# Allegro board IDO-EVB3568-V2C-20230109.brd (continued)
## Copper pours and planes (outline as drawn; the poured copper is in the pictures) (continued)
GND on BOTTOM (solid shape): 56.16,23.3 56.26,23.24 56.23,23.13 52.83,19.73 52.83,18.8 52.35,18.8 51.9,18.35 51.79,18.33 51.73,18.42 51.73,19.27 55.76,23.3
GND on BOTTOM (solid shape): 82.34,74.36 82.37,74.27 82.32,74.2 82.23,74.12 82.15,74.01 79.57,74.01 79.33,74.25 79.3,74.37 79.4,74.43 82.27,74.43
GND on BOTTOM (solid shape): 19.41,51.13 19.53,51.15 19.59,51.06 19.59,49.47 20.12,49.47 20.54,49.05 20.54,48.94 20.57,48.91 20.58,48.85 20.53,48.82 18.69,48.82 18.53,48.67 18.06,48.67 18.06,49.78
GND on BOTTOM (solid shape): 21.93,26.31 22,26.4 22.11,26.38 22.75,25.73 23.95,25.73 24.32,25.37 24.32,24.7 23.3,23.68 23.3,22.92 23.22,22.84 23.11,22.82 23.05,22.91 23.05,24.98 21.93,26.09
GND on BOTTOM (solid shape): 53.79,24.83 53.84,24.8 53.83,24.74 52.16,23.08 51.96,23.08 51.9,23.15 51.83,23.21 51.78,23.29 51.83,23.38 51.9,23.44 51.96,23.51 52.33,23.51 53.65,24.83
GND on BOTTOM (solid shape): 89.09,23.79 90.33,23.79 90.43,23.73 90.41,23.62 90.23,23.44 85.97,23.44 85.88,23.51 85.9,23.62 86.43,24.14 88.73,24.14
GND on BOTTOM (solid shape): 111.15,68.77 111.23,68.73 111.25,68.64 111.24,68.43 111.33,68.24 108.96,65.87 108.03,65.87 107.93,65.94 107.95,66.05 110.68,68.77
GND on BOTTOM (solid shape): 19.91,37.83 19.95,37.68 20.03,37.56 20.06,37.49 20.04,37.42 19.96,37.31 19.92,37.18 19.92,37.14 19.73,37.14 19.61,37.26 19.53,37.26 19.53,37.36 17.9,37.36 17.9,37.65 19.53,37.65 19.53,37.84 19.56,37.87 19.91,37.87
GND on BOTTOM (solid shape): 27.81,66.62 27.83,66.51 27.74,66.45 27.66,66.45 27.05,67.06 23.46,67.06 23.36,67.11 23.38,67.22 23.44,67.34 23.47,67.47 23.48,67.51 26.92,67.51
GND on BOTTOM (solid shape): 19.89,39.33 19.95,39.19 20.05,39.07 20.09,39 20.06,38.92 19.97,38.81 19.92,38.68 19.91,38.64 19.53,38.64 19.53,38.64 19.53,38.86 17.9,38.86 17.9,39.15 19.53,39.15 19.53,39.37 19.54,39.37 19.89,39.37
GND on BOTTOM (solid shape): 23.96,14.55 24,14.6 24.05,14.59 25.11,13.53 27.89,13.53 28.16,13.26 28.16,12.82 28.65,12.33 28.65,11.49 29.27,10.87 29.27,10.74 29.21,10.65 29.1,10.67 26.48,13.3 25.18,13.3 23.96,14.51
GND on BOTTOM (solid shape): 28.51,16.61 28.57,16.71 28.68,16.68 29.02,16.35 29.02,15.21 30.16,14.06 30.16,12.79 30.59,12.36 30.59,11.62 30.53,11.53 30.42,11.55 29.94,12.03 29.94,12.86 29.45,13.35 29.45,13.8 28.51,14.74
GND on BOTTOM (solid shape): 55.55,13.28 55.87,13.28 57.14,13.28 57.31,13.28 58.37,13.28 58.47,13.18 58.47,12.91 58.34,12.78 56.44,12.78 56.14,13.08 55.47,13.08 55.16,12.78 55.12,12.78 54.82,13.08 54.65,13.08 54.55,13.14 54.58,13.25 54.84,13.52 54.84,13.73 55.1,13.73
GND on BOTTOM (solid shape): 19.93,36.33 19.97,36.22 20.04,36.12 20.07,36.05 20.04,35.98 19.94,35.85 19.9,35.71 19.89,35.66 19.59,35.66 19.53,35.72 19.53,35.86 17.9,35.86 17.9,36.07 18.04,36.07 18.12,36.15 19.53,36.15 19.53,36.25 19.61,36.25 19.73,36.37 19.92,36.37
GND on BOTTOM (solid shape): 19.94,40.85 19.97,40.73 20.03,40.62 20.05,40.55 20.02,40.49 19.93,40.35 19.88,40.18 19.88,40.14 19.56,40.14 19.53,40.16 19.53,40.36 18.02,40.36 17.99,40.39 17.95,40.39 17.95,40.6 18,40.65 19.53,40.65 19.53,40.89 19.93,40.89
GND on BOTTOM (solid shape): 46.87,61.28 46.96,61.22 46.94,61.11 46.31,60.48 46.31,59.97 46.27,59.96 46.14,59.92 46.03,59.85 46,59.84 45.96,59.85 45.85,59.92 45.72,59.96 45.68,59.97 45.68,60.14 46.82,61.28
GND on BOTTOM (solid shape): 79.59,47.44 79.64,47.53 79.75,47.52 79.86,47.47 79.99,47.45 80.02,47.44 80.04,47.4 80.04,46.92 83.34,43.61 83.35,43.55 83.31,43.52 83.24,43.52 79.59,47.18
GND on BOTTOM (solid shape): 61.8,37.78 61.89,37.72 61.87,37.61 61.18,36.92 57.21,36.92 56.96,37.17 56.93,37.27 57,37.34 57.22,37.49 57.32,37.74 57.33,37.78
GND on BOTTOM (solid shape): 87.06,28.97 87.12,28.98 87.15,28.94 87.15,28.9 85.75,27.51 85.75,26.62 76.48,17.35 76.48,13.16 70.05,6.73 38.74,6.73 35.92,9.55 35.92,9.58 35.95,9.63 36,9.62 37.59,8.03 38.05,8.03 39.19,6.88 70.05,6.88 76.07,12.9 76.07,17.09 85.62,26.65 85.62,27.53
GND on BOTTOM (solid shape): 123.24,63.69 123.3,63.78 123.41,63.76 123.64,63.53 123.65,63.53 123.65,60.94 125.17,59.41 125.2,59.34 125.16,59.26 125.06,59.13 125,58.97 125,58.93 124.79,58.93 123.24,60.48
GND on BOTTOM (solid shape): 100.27,18.89 100.27,13.28 100.2,13.19 100.09,13.21 99.78,13.52 99.78,17.71 97.96,19.54 97.96,19.57 97.94,19.78 97.84,19.96 97.82,20.07 97.91,20.13 99.03,20.13
GND on BOTTOM (solid shape): 55.16,54.92 55.22,54.83 55.22,54.49 53.92,53.19 53.85,53.19 53.75,53.25 53.77,53.36 53.87,53.46 53.87,53.71 53.91,53.75 54.31,53.75 54.74,54.17 54.74,54.76 54.78,54.77 54.92,54.81 55.04,54.9
GND on BOTTOM (solid shape): 48.65,27.08 48.71,27.17 48.82,27.15 49.72,26.25 49.72,25.04 49.68,24.96 49.59,24.94 49.2,24.89 48.98,24.56 48.98,24.52 48.65,24.52
GND on BOTTOM (solid shape): 119.21,66.56 119.28,66.66 119.39,66.63 119.47,66.55 120.66,66.55 120.73,66.62 120.78,66.63 120.82,66.58 120.82,64.13 121.09,63.85 121.09,59.89 121.03,59.8 120.92,59.82 120.91,59.83 119.52,59.83 119.21,60.13 119.21,60.65 120.92,60.65 120.92,62.89 119.21,62.89
GND on BOTTOM (solid shape): 82.24,71.71 85.17,71.71 86.09,70.8 86.09,69.97 86.9,69.16 87.18,69.16 87.2,69.1 87.2,69.04 86.3,69.04 84.54,70.81 82.49,70.81 82.4,70.85 82.39,70.94 82.34,71.26 82.09,71.46 82.05,71.47 82.05,71.63 81.35,72.34 81.32,72.45 81.42,72.51 81.44,72.51
GND on BOTTOM (solid shape): 42.32,22.76 42.41,22.79 42.48,22.73 42.66,22.51 42.92,22.43 43.01,22.37 42.99,22.26 42.9,22.16 41.38,22.16 41.11,22.43 40.46,22.43 40.38,22.47 40.37,22.56 40.38,22.65 42.2,22.65 42.2,22.75 42.31,22.75
GND on BOTTOM (solid shape): 99.69,43.81 99.69,43.3 100.45,42.54 102.84,42.54 102.9,42.49 102.9,42.35 102.48,41.94 100.58,41.94 100.2,41.56 100.2,41.29 100.14,41.19 100.03,41.22 100.01,41.24 97.98,41.24 97.77,41.45 97.74,41.55 97.82,41.62 98.09,41.78 98.2,42.08 98.2,42.1 98.72,42.61 98.72,44.68 98.77,44.73
GND on BOTTOM (solid shape): 57.23,21.77 57.33,21.71 57.3,21.59 55.65,19.94 55.65,18.92 55.42,18.69 55.42,17.87 55.35,17.79 55.35,17.13 55.42,17.05 55.42,16.67 55.38,16.67 55.24,16.62 55.13,16.54 55.09,16.52 55.06,16.54 54.9,16.64 54.71,16.68 54.68,16.69 54.66,16.73 54.66,16.83 54.81,16.99 54.81,17.45 54.66,17.6 54.66,18.74 54.49,18.92 54.49,19.2 57.05,21.77
GND on BOTTOM (solid shape): 67.71,46.25 67.82,46.27 67.88,46.18 67.88,45.75 66.36,44.23 66.36,43.01 65.01,41.66 65.01,41.08 64.86,40.93 64,40.93 63.92,40.98 63.91,41.08 63.94,41.16 63.95,41.26 63.95,41.28 64.08,41.41 64.39,41.41 64.39,41.5 64.49,41.5 64.49,42.2 64.68,42.4 64.68,43.45 64.43,43.7 64.41,43.81 64.5,43.87 65.31,43.87 65.34,43.88
GND on BOTTOM (solid shape): 76.15,50.75 76.18,50.73 76.39,50.58 76.64,50.56 76.64,50.56 77.99,50.56 78.2,50.35 78.23,50.26 78.17,50.18 78,50.07 77.89,49.91 77.87,49.87 75.26,49.87 75.17,49.94 75.19,50.05 75.82,50.68 75.84,50.68 75.98,50.69 76.11,50.74
GND on BOTTOM (solid shape): 77.25,75.25 77.28,75.14 77.18,75.08 74.11,75.08 73.77,74.73 73.65,74.73 73.57,74.78 73.56,74.88 73.59,75.22 73.38,75.49 72.95,75.92 70.21,75.92 69.65,75.36 69.13,75.36 69.04,75.45 68.92,75.51 68.86,75.58 68.89,75.67 69.32,76.1 76.4,76.1
GND on BOTTOM (solid shape): 21.96,14.16 22.03,14.06 22.03,13.55 22.5,13.09 22.52,12.98 22.43,12.92 20.13,12.92 19.82,13.23 19.8,13.35 19.92,13.39 21,13.43 21.85,14.11
GND on BOTTOM (solid shape): 10.41,62.63 10.41,62.15 10.92,61.64 10.94,61.53 10.85,61.47 10.79,61.47 10.24,60.92 10.24,60.34 10.49,60.09 10.49,58.52 10.21,58.52 10.21,59.01 8.82,60.4 7.81,60.4 7.72,60.45 7.73,60.56 7.84,60.83 7.85,61.12 7.91,61.23 8.03,61.21 8.33,60.91 9.25,60.91 9.65,61.31 9.65,62.71 9.86,62.92 10.13,62.92
GND on BOTTOM (solid shape): 22.52,24.76 22.52,22.92 21.53,21.93 21.53,18.75 21.46,18.65 21.35,18.67 21.01,19.01 19.87,19.01 18.76,20.13 18.76,21.3 19.52,22.06 19.52,24.73 20.03,25.24 20.12,25.27 20.2,25.2 20.76,24.88 21.12,25.42 21.12,25.44 21.48,25.8
GND on BOTTOM (solid shape): 62.32,35.19 62.38,35.28 62.49,35.26 62.53,35.22 62.59,35.19 63.36,34.42 66.86,34.42 66.87,34.41 67,34.4 67.12,34.41 67.21,34.39 67.25,34.31 67.25,33.59 67.15,33.49 62.83,33.49 62.45,33.11 59.36,33.11 59.27,33.16 59.28,33.27 59.34,33.42 59.35,33.6 59.35,33.62 59.57,33.85 61.02,33.85 62.32,35.14
GND on BOTTOM (solid shape): 92.24,17.91 93.11,17.91 93.42,17.6 93.44,17.49 93.35,17.42 91.48,17.42 91.14,17.57 90.79,17.42 89.68,17.42 89.03,16.77 89.03,15.41 88.91,15.23 88.88,15.02 88.88,14.99 88.83,14.94 88.77,15 88.77,18.02 88.1,18.69 83.7,18.69 83.57,18.83 83.55,18.94 83.65,19 91.15,19
GND on BOTTOM (solid shape): 62.88,64.1 62.99,64.13 63.06,64.03 63.06,62.75 62.87,62.56 62.87,62.55 62.76,62.44 62.75,62.44 62.63,62.32 62.32,62.32 62.24,62.23 62.13,62.21 62.06,62.31 62.06,62.36 62.1,62.37 62.4,62.77 62.18,63.22 62.13,63.3 62.16,63.38
GND on BOTTOM (solid shape): 52.37,17.19 52.46,17.22 52.53,17.17 52.58,17.11 52.64,17.05 52.67,16.98 52.64,16.9 52.39,16.65 52.39,14.39 51.93,13.93 51.17,13.93 51.08,13.99 51.1,14.1 51.23,14.42 51.11,14.74 51.1,14.85 51.19,14.91 51.5,14.91 52.13,15.54 52.13,16.96
GND on BOTTOM (solid shape): 51.27,22.26 51.31,22.34 51.4,22.36 51.47,22.34 51.55,22.33 51.64,22.27 51.61,22.16 49.7,20.24 49.7,19.71 48.65,19.71 48.65,19.79 48.67,19.83 48.7,19.84 49.06,20.02 49.16,20.41 49.18,20.5 49.26,20.54 49.62,20.54 51.27,22.19
GND on BOTTOM (solid shape): 94.73,22.15 94.73,20.99 94.67,20.9 94.56,20.92 94.5,20.98 92.36,20.98 91.98,21.36 91.98,21.39 92,21.43 92.03,21.44 92.5,21.99 91.89,22.38 91.88,22.38 86.63,22.38 86.56,22.44 86.55,22.5 86.6,22.53 90.61,22.53 91.15,23.06 93.82,23.06
GND on BOTTOM (solid shape): 101.61,69.31 101.63,69.26 101.58,69.23 101.48,69.23 100.42,70.29 97.15,70.29 95.93,69.08 95.18,69.08 95.1,69.11 95.08,69.2 94.7,69.79 94.14,69.37 94.13,69.33 93.84,69.33 92.8,68.29 92.7,68.29 92.61,68.35 92.63,68.46 94.57,70.4 100.53,70.4
GND on BOTTOM (solid shape): 69.29,60.28 69.28,60.25 69.41,59.81 69.84,59.68 69.93,59.66 69.96,59.58 69.96,59.47 68.59,58.09 68.48,58.07 68.41,58.17 68.41,59.02 68.54,59.15 68.54,59.7 68.57,59.71 68.83,59.99 68.8,60.37 68.8,60.47 68.89,60.52 69.05,60.52
GND on BOTTOM (solid shape): 18.76,18.36 18.82,18.46 18.93,18.44 19.4,17.97 20.54,17.97 22.03,16.48 22.03,16.05 21.96,15.95 21.85,15.99 20.39,16.78 18.95,15.99 18.83,15.94 18.76,16.04
GND on BOTTOM (solid shape): 32.59,27.62 32.68,27.56 32.66,27.45 32.58,27.37 31.94,27.37 31.18,26.6 31.18,24.67 31.01,24.5 30.43,24.5 30.43,23.74 30.37,23.64 30.26,23.66 29.18,24.74 27,24.74 26.59,25.15 26.59,26.52 26.48,26.63 26.46,26.74 26.56,26.8 26.99,27.01 27.03,27.48 27.04,27.58 27.12,27.62
GND on BOTTOM (solid shape): 87.9,28.28 88.02,28.3 88.06,28.18 87.96,26.67 88.7,25.36 88.73,25.25 88.63,25.18 86,25.18 84.89,24.07 84.87,24.07 83.77,22.98 83.77,22.96 81.6,20.79 81.6,20.51 81.12,20.03 80.74,20.03 77.91,17.2 77.91,15.55 77.64,15.28 77.53,15.26 77.47,15.35 77.47,16.97 86.69,26.19 86.69,27.08
GND on BOTTOM (solid shape): 85.05,75.2 85.17,75.08 85.2,75 85.15,74.93 85.05,74.3 85.69,74.27 85.76,74.3 85.84,74.27 85.95,74.19 86.07,74.15 86.09,74.14 86.14,74.1 86.03,73.98 84.65,73.98 84.41,74.23 84.41,74.97 84.37,75.01 84.42,75.06 84.44,75.06 84.72,75.12 84.96,75.28 84.97,75.3 85.05,75.3
GND on BOTTOM (solid shape): 11.17,40.19 11.2,40.17 11.23,40.11 11.27,40.06 11.28,40.03 11.27,40 11.43,39.25 12.1,39.6 12.11,39.64 12.4,39.64 12.4,39.21 12.8,38.81 14.03,38.81 14.43,39.21 14.43,39.56 14.47,39.6 16.04,39.6 16.04,39.31 17.86,39.31 17.86,39.16 16.04,39.16 16.04,38.61 11.69,38.61 10.87,39.42 10.87,40.05 10.9,40.12 10.97,40.15 11.05,40.16 11.14,40.19
GND on BOTTOM (solid shape): 88.99,69.22 89.01,69.11 88.92,69.04 88.13,69.04 88.05,69.08 88.03,69.16 88.01,69.37 87.9,69.55 87.84,70.16 87.23,70.07 87.16,70.03 87.08,70.06 86.85,70.29 86.85,71.11 85.59,72.37 85.58,72.43 85.62,72.46 85.74,72.46
GND on BOTTOM (solid shape): 61.93,54.22 61.99,54.2 62.18,54.1 62.4,54.09 62.48,54.07 62.52,53.99 62.52,49.23 61.84,48.55 61.39,48.55 61.3,48.6 61.3,48.7 61.36,48.95 61.29,49.2 61.29,49.3 61.38,49.35 61.52,49.35 62.1,49.93 62.1,53.19 61.38,53.91 61.36,54.03 61.47,54.09 61.68,54.1 61.86,54.2
GND on BOTTOM (solid shape): 39.69,12.11 39.73,12.09 40.05,11.95 40.37,12.07 40.45,12.09 40.52,12.06 40.63,11.97 40.78,11.92 40.82,11.91 40.82,11.07 41.42,10.46 43.77,10.46 44.68,11.38 45.15,11.38 45.24,11.32 45.22,11.21 43.53,9.51 40.78,9.51 40.58,9.71 40.58,10.4 40.14,10.83 39.07,10.83 38.85,11.06 38.85,11.98 38.91,12.07 39.01,12.06 39.34,11.95 39.65,12.09
GND on BOTTOM (solid shape): 88.42,10.39 88.51,10.32 88.48,10.21 88.35,9.61 88.91,9.37 88.91,9.37 92.41,9.37 92.5,9.31 92.48,9.2 92.24,8.97 91.25,8.97 90.42,8.14 90.42,6.6 90.57,6.45 90.31,6.18 87.61,6.18 87.52,6.26 87.55,6.37 87.75,6.78 87.51,7.17 87.51,9.99 87.91,10.39
GND on BOTTOM (solid shape): 52.91,41.28 53.02,41.31 53.09,41.21 53.09,38.37 54.97,36.48 54.98,36.43 54.99,36.38 54.99,36.33 54.57,35.91 54.46,35.89 54.39,35.98 54.39,36.43 54.14,36.69 54.14,36.71 53.53,37.24 53.32,36.46 53.33,36.42 53.31,36.39 53.17,36.01 53.36,35.66 53.38,35.64 53.38,35.57 52.97,35.16 52.86,35.14 52.79,35.23 52.79,41.16
GND on BOTTOM (solid shape): 108.92,28.45 109.02,28.43 109.23,28.21 109.79,28.21 109.88,28.15 109.86,28.04 106.29,24.47 106.29,17.76 101.35,12.83 101.24,12.81 101.18,12.9 101.18,19.11 99.57,20.72 99.57,23.13 99.61,23.2 99.69,23.23 99.98,23.27 100.19,23.47 100.19,23.47 100.36,23.64 100.36,24.04 100.4,24.13 100.49,24.14 100.99,24.24 101.12,24.72 101.12,24.73 101.12,25.57 103.54,27.99 105.76,27.99 105.77,27.99 105.9,27.97 106.04,27.99 106.04,27.99 108.52,27.99 108.61,28.08 108.61,28.08 108.76,28.21 108.85,28.38
GND on BOTTOM (solid shape): 53.64,19.46 53.69,19.47 53.73,19.42 53.73,18.6 53.9,18.43 53.9,16.71 53.88,16.67 53.85,16.66 53.4,16.25 53.71,15.73 53.74,15.72 53.74,15.63 53.74,15.63 53.74,13.73 53.82,13.66 53.8,13.55 53.66,13.41 52.41,13.41 52.32,13.47 52.34,13.58 52.92,14.16 52.92,16.42 53.3,16.81 53.3,17.09 53.28,17.75 52.62,17.77 52.57,17.76 52.54,17.8 52.54,17.91 52.66,18.03 53.19,18.03 53.59,18.43 53.59,19.41
GND on BOTTOM (solid shape): 125.75,51.86 125.86,51.88 125.92,51.79 125.92,51.36 125.88,51.35 125.5,50.68 126.26,50.53 126.37,50.54 126.43,50.45 126.43,49.59 126.31,49.47 125.8,49.47 125.71,49.52 125.71,49.62 125.69,50.13 125.23,50.33 125.21,50.33 124.93,50.61 124.93,51.13 124.97,51.21 125.06,51.23 125.51,51.33 125.67,51.76 125.67,51.78
GND on BOTTOM (solid shape): 77.14,72.14 77.17,72.06 77.12,71.98 76.97,71.36 77.61,71.29 78.27,71.39 78.02,72.01 77.99,72.02 77.99,72.11 78.05,72.21 78.16,72.18 78.61,71.74 80.87,71.74 81.1,71.5 81.13,71.43 81.1,71.36 80.98,71.16 80.97,70.94 80.96,70.85 80.88,70.81 77.03,70.81 76.5,71.34 76.5,71.63 75.83,72.3 75.81,72.41 75.9,72.47 76.82,72.47
GND on BOTTOM (solid shape): 90.79,16.76 91.14,16.62 91.48,16.76 93.46,16.76 93.78,16.45 93.78,12.71 92.12,11.05 87.97,11.05 87.92,11.08 87.93,11.14 87.97,11.18 89.95,11.18 90.73,11.95 90.73,14.92 90.73,14.93 90.74,15.17 90.62,15.39 90.6,15.5 90.7,15.56 92.15,15.56 92.22,15.53 92.25,15.45 93.09,15.14 92.66,15.92 92.64,15.92 92.46,16.09 90.66,16.09 90.59,16.16 90.59,16.19 90.57,16.41 90.46,16.59 90.44,16.7 90.53,16.76
GND on BOTTOM (solid shape): 33.89,21.9 34.29,21.5 34.29,19.16 34.01,18.58 34.56,18.25 34.65,18.23 34.68,18.15 34.68,17.55 34.62,17.45 34.51,17.48 33.8,17.45 33.9,16.75 33.9,16.32 33.59,16.01 33.59,14.66 32.91,13.98 32.91,12.94 32.84,12.85 32.73,12.87 32.17,13.43 32.17,13.46 32.02,13.88 31.58,13.99 31.5,14.01 31.46,14.09 31.46,14.66 30.56,15.57 30.56,18.21 30.65,18.21 30.65,19.59 30.68,19.62 32.67,19.62 33.48,20.43 33.51,20.43 33.51,22.39 33.47,22.39 33.47,22.56 33.56,22.64 33.89,22.64
GND on BOTTOM (solid shape): 60.76,34.58 60.85,34.52 60.83,34.41 60.8,34.38 59.35,34.38 58.97,34 58.94,34 58.42,33.66 58.69,33.09 58.74,33.02 58.72,32.92 58.52,32.73 58.49,32.73 58.18,32.67 57.98,32.42 57.9,32.35 57.81,32.38 57.11,33.08 57.11,33.21 57.17,33.96 56.43,33.83 56.34,33.78 56.25,33.83 56.11,33.99 55.91,34.08 55.83,34.14 55.86,34.25 56.19,34.58
GND on BOTTOM (solid shape): 73.26,63.63 73.29,63.54 73.23,63.47 73.05,62.79 73.74,62.66 73.77,62.67 73.81,62.65 73.87,62.6 73.93,62.56 73.99,62.49 73.96,62.4 72.17,60.61 72.16,60.61 72.07,60.57 71.98,60.52 71.88,60.5 71.82,60.6 71.82,61.15 72.22,61.56 72.22,62.49 72.25,62.56 72.32,62.59 72.62,63.43 71.84,63 71.84,62.98 71.8,62.94 71.75,62.92 71.72,62.97 71.72,63.72 71.94,63.94 72.94,63.94
GND on BOTTOM (solid shape): 42.05,14.47 42.96,14.47 43.35,14.2 43.77,14.4 43.85,14.45 43.93,14.42 44.13,14.21 44.52,14.21 44.56,14.16 44.6,14.11 44.63,14 44.53,13.93 41.86,13.93 41.78,13.97 41.76,14.06 41.06,14.59 41.17,13.71 41.18,13.71 41.3,13.6 41.32,13.49 41.22,13.42 40.79,13.42 40.39,13.82 39.8,13.82 39.36,13.38 39.36,12.96 39.34,12.92 39.31,12.91 39.15,12.88 39.01,12.8 38.91,12.79 38.85,12.88 38.85,13.94 39.12,14.21 40.29,14.21 40.85,14.77 41.75,14.77
GND on BOTTOM (solid shape): 51.33,45.72 51.44,45.74 51.5,45.65 51.5,45.46 48.07,42.03 48.07,37.05 48.22,36.9 48.24,36.79 48.15,36.73 46.68,36.73 46.59,36.78 46.59,36.88 45.84,38.01 45.35,36.75 44.83,36.23 44.83,28.33 44.77,28.24 44.66,28.26 44.49,28.43 44.49,33.77 43.65,34.6 43.65,35.95 43.69,36.03 43.78,36.05 44.18,36.08 44.41,36.4 44.41,36.41 44.97,36.97 44.97,37.94 45.55,38.52 45.55,40.17 45.94,40.55 45.94,44.56 45.78,44.72 45.76,44.83 45.85,44.89 50.5,44.89
GND on BOTTOM (solid shape): 9.8,29.19 9.87,29.28 9.98,29.26 11.93,27.3 14.34,27.3 14.6,27.04 14.6,24.5 15.49,23.61 15.49,19.42 16.84,18.08 16.84,18.01 16.81,17.97 16.75,17.98 14.63,20.1 14.63,22.64 12.86,24.41 11.8,24.41 11.6,24.21 11.55,24.16 11.43,24.04 11.43,23.97 11.43,23.96 11.41,23.83 11.43,23.69 11.43,23.68 11.43,23.08 11.43,23.07 11.41,22.94 11.43,22.8 11.43,22.8 11.43,22.19 11.43,22.18 11.41,22.05 11.43,21.91 11.43,21.91 11.43,21.3 11.43,21.29 11.41,21.16 11.43,21.02 11.43,21.02 11.43,20.41 11.43,20.4 11.41,20.27 11.43,20.14 11.43,20.13 11.43,19.68 12.06,19.05 12.95,19.05 14.16,17.84 14.19,17.76 14.16,17.69 14.03,17.5 14,17.27 14.01,17.24 13.91,17.14 13.91,14.73 13.85,14.63 13.74,14.65 13.58,14.75 13.4,14.78 13.33,14.81 13.3,14.88 13.3,15.4 10.95,17.75 10.95,23.66 10.45,24.16 9.58,24.16 9.48,24.22 9.5,24.33 9.8,24.63
GND on BOTTOM (solid shape): 13.11,42.67 13.2,42.62 13.2,42.51 13.12,42.17 13.29,41.87 13.32,41.79 13.29,41.71 13.29,40.97 14.02,41.13 14.09,41.19 14.18,41.16 14.68,40.66 16.04,40.66 16.04,40.41 14.2,40.41 13.67,39.87 13.67,39.57 13.16,39.57 13.16,39.97 12.73,40.4 12.11,40.4 12.11,40.44 11.86,40.8 11.44,40.81 11.4,40.81 11.37,40.84 10.99,41.1 10.57,40.93 10.49,40.89 10.41,40.93 10.19,41.08 9.93,41.09 9.84,41.11 9.8,41.19 9.8,42.41 10.07,42.67
GND on BOTTOM (solid shape): 35.11,16.39 35.22,16.41 35.28,16.32 35.28,14.05 34.98,13.74 34.98,9.09 38.24,5.82 38.26,5.71 38.17,5.65 37.8,5.65 35.37,8.09 31.33,8.09 31.25,8.17 31.22,8.28 31.32,8.35 31.56,8.4 31.74,8.56 31.84,8.56 32.88,9.59 32.88,10.18 32.92,10.26 33.01,10.28 33.49,10.44 33.56,10.94 33.56,11.02 33.62,11.08 33.65,11.08 33.68,11.08 33.71,11.06 34.33,10.83 34.59,11.44 34.58,11.47 34.82,11.71 34.82,15.22 34.85,15.23 35.15,15.62 34.95,16.06 34.9,16.14 34.93,16.22
GND on BOTTOM (solid shape): 106.82,48.53 106.85,48.42 106.75,48.36 106.55,48.33 106.38,48.22 106.31,48.18 106.24,48.22 105.56,48.23 105.55,47.55 105.57,47.44 105.48,47.38 100.6,47.38 99.36,46.13 98.23,46.13 98.14,46.18 98.14,46.28 98.19,46.53 98.11,46.77 98.11,46.82 98.15,46.85 98.21,46.85 98.94,47.59 102.37,47.59 103.15,48.36 103.25,48.39 103.32,48.31 103.65,47.93 104.14,48.05 104.21,48.08 104.28,48.05 104.87,47.97 105.09,48.52 105.1,48.61 105.18,48.65 106.71,48.65
GND on BOTTOM (solid shape): 39.33,19.4 39.43,19.43 39.5,19.36 39.83,19.04 40.28,19.15 42.05,19.15 42.05,18.56 42.41,18.2 42.41,18.2 42.74,17.87 44.94,17.87 45.03,17.82 45.03,17.72 44.92,17.26 45.03,16.8 45.03,16.71 44.97,16.66 44.67,16.29 44.82,15.85 44.85,15.73 44.75,15.67 44.47,15.67 43.82,16.32 40.02,16.32 40.01,16.36 39.39,16.61 39.27,15.95 39.35,15.28 39.98,15.52 39.99,15.56 40.13,15.56 40.23,15.49 40.2,15.38 39.82,15 38.65,15 38.41,14.76 38.3,14.74 38.24,14.83 38.24,18.3
GND on BOTTOM (solid shape): 75.07,62.37 75.16,62.4 75.23,62.34 75.31,62.22 75.41,62.13 75.41,61.66 73.34,59.6 73.34,55.12 73.3,55.04 73.22,55.02 72.66,54.75 72.83,54.16 72.83,53.65 70.87,51.69 70.76,51.67 70.7,51.77 70.7,52.92 71.87,54.09 71.87,54.16 71.68,55.03 71.22,54.27 71.25,54.23 70.37,53.34 70.26,53.32 70.19,53.42 70.19,53.56 70.7,54.07 70.7,57.5 71.82,58.61 71.82,59.7 71.88,59.79 71.98,59.78 72.29,59.67 72.63,59.8 72.66,59.78 73.32,59.82 73.32,60.48 73.29,60.55 73.32,60.62
GND on BOTTOM (solid shape): 13.09,61.61 14.94,61.61 14.94,61.01 15.01,60.93 14.96,60.88 14.94,60.88 14.77,60.85 14.62,60.76 14.3,60.88 13.98,60.76 13.34,60.76 13.28,60.12 13.34,59.49 13.98,59.48 14.3,59.36 14.62,59.48 15.26,59.49 15.32,60.12 15.4,60.31 15.4,60.52 15.4,60.58 15.53,60.58 15.53,60.08 17.39,60.08 17.39,60.63 18.16,60.63 18.29,60.5 18.29,60.31 18.25,60.3 17.96,60.06 17.94,59.67 17.92,59.58 17.84,59.54 17.7,59.54 17.56,59.4 17.45,59.38 17.39,59.47 17.39,59.61 15.53,59.61 15.53,59.13 15.24,59.13 15.14,59.04 13.19,59.04 13.19,58.99 13.12,58.99 12.99,58.87 12.84,58.87 12.74,58.93 12.76,59.04 13.06,59.33 13.06,60.03 12.66,60.43 12.19,60.43 12.19,60.86 11.78,61.27 11.76,61.38 11.86,61.44 12.68,61.44 13.01,61.77 13.09,61.77
GND on BOTTOM (solid shape): outline of 191 points within 72.36,6.18 89.81,19.76
GND on BOTTOM (solid shape): 124.92,34.33 124.92,29.74 125.01,29.64 124.95,29.58 124.92,29.59 121.15,27.8 123.87,24.63 123.95,24.6 123.98,24.53 123.98,23.97 124.03,23.92 124.04,23.86 123.99,23.83 123.12,23.83 119.08,27.87 119.08,29.01 119.1,29.05 119.13,29.06 119.56,29.73 118.77,29.87 118.7,29.84 118.63,29.87 118.48,29.98 118.3,30.02 118.21,30.08 118.24,30.19 120.43,32.38 121.19,32.38 122.06,33.26 122.17,33.28 122.24,33.19 122.24,32.1 123.3,31.03 123.3,31 124.11,30.6 123.71,31.41 123.68,31.41 122.77,32.32 122.77,35.76 123.49,35.76
GND on BOTTOM (solid shape): 98.77,27.16 98.77,21.68 98.31,21.22 97.88,21.22 97.46,21.43 97.07,21.18 97.06,21.18 97.02,21.14 96.96,21.19 96.97,21.22 96.16,21.62 96.56,20.81 96.59,20.82 97.22,20.18 97.25,20.1 97.21,20.02 97.04,19.46 97.55,19.16 97.58,19.16 99.25,17.49 99.25,13.3 99.76,12.79 99.76,9.74 100.34,9.16 100.34,7.83 100.32,7.8 100.21,7.78 100.14,7.86 100.05,8.09 99.85,8.24 99.83,8.26 99.82,8.3 99.34,8.91 98.92,8.25 98.91,8.16 98.83,8.12 98.48,8.12 98.19,7.83 98.08,7.81 98.02,7.9 98.02,18.05 95.64,20.42 95.64,22.53 94.19,23.98 93.98,23.98 93.98,24.45 95.64,26.1 96.41,26.1 96.42,26.1 97.03,26.56 96.42,27.02 96.41,27.02 95.87,27.02 95.77,27.08 95.8,27.19 96.2,27.6 98.33,27.6
GND on BOTTOM (solid shape): 61.82,19.99 61.92,19.93 61.9,19.82 61.04,18.96 60.95,18.93 60.87,18.99 60.18,19.23 60.06,18.51 60.07,18.48 60.06,18.45 60.01,17.9 60.5,17.66 60.6,17.63 60.61,17.53 60.82,16.94 61.43,17.05 61.51,17.09 61.58,17.05 62.33,17.05 62.17,17.78 62.12,17.85 62.14,17.94 62.26,18.06 62.37,18.08 62.43,17.98 62.43,17.93 62.71,17.65 63.17,17.65 63.45,17.93 63.45,18.24 63.77,18.24 63.86,18.17 63.84,18.06 62.27,16.5 62.25,16.5 61.75,16.24 61.84,15.69 61.86,15.58 61.77,15.52 60.59,15.52 59.97,16.14 59.97,17.54 59.3,18.21 59.3,18.21 58.92,18.46 58.5,18.28 58.39,18.24 58.32,18.34 58.32,19.25 59.06,19.99
GND on BOTTOM (solid shape): 28.83,23.13 28.83,22.31 28.83,22.31 29.04,21.76 29.63,21.84 29.69,21.87 29.76,21.85 30.37,21.88 30.45,22.49 30.45,22.59 30.54,22.64 30.94,22.64 30.94,22.39 30.9,22.39 30.9,20.92 29.3,20.92 28.69,20.31 28.66,20.29 28.62,20.31 27.96,20.31 27.93,19.64 27.93,18.92 27.87,18.82 27.76,18.84 27.34,19.27 24.7,19.27 24.57,19.39 24.55,19.5 24.64,19.56 25,19.76 25.07,20.17 25.07,20.18 25.07,20.87 25.69,21.49 25.77,21.52 25.84,21.47 26.15,21.27 26.51,21.35 27.18,21.4 27.14,22.07 27.12,22.11 27.14,22.15 26.88,22.92 26.31,22.35 26.29,22.26 26.21,22.22 26.13,22.21 26.05,22.18 25.95,22.19 25.91,22.28 25.91,22.47 26.81,23.37 28.59,23.37
GND on BOTTOM (solid shape): 78.06,49.34 78.15,49.29 78.25,49.26 78.3,49.25 78.3,47.19 78.23,47.1 78.12,47.12 76.74,48.5 76.74,48.52 76.22,48.86 75.8,48.41 75.78,48.37 75.75,48.36 75.3,47.96 75.6,47.43 75.66,47.35 75.62,47.25 75.56,46.52 76.29,46.6 76.75,46.6 78.91,44.43 78.94,44.32 78.84,44.26 75.36,44.26 75.35,44.3 74.67,44.68 74.54,43.91 74.55,43.88 74.54,43.84 74.66,43.08 75.35,43.43 75.36,43.47 79.11,43.47 81.43,41.16 81.45,41.05 81.36,40.98 77.18,40.98 75.89,39.69 75.78,39.67 75.72,39.76 75.72,41.69 75.36,42.05 75.36,42.07 74.54,42.4 74.87,41.58 74.89,41.58 75.06,41.42 75.06,39.71 74.89,39.54 74.87,39.54 74.69,39.5 74.53,39.4 74.31,39.4 74.21,39.46 74.24,39.57 74.26,39.59 74.26,48.71 74.89,49.34
GND on BOTTOM (solid shape): outline of 84 points within 52.9,10.64 70.3,21.03
GND on BOTTOM (solid shape): outline of 99 points within 78.82,44.28 94.4,60.92
GND on BOTTOM (solid shape): outline of 489 points within 37.65,8.18 83.53,26.49
GND on BOTTOM (solid shape): outline of 862 points within 100.8,7.04 128.3,29.25
GND on BOTTOM (solid shape): outline of 874 points within 32.49,22.81 45.15,45.51
GND on BOTTOM (solid shape): outline of 3634 points within 3.39,14.31 34.48,70.07
GND on BOTTOM (solid shape): outline of 6369 points within 0.25,0.25 134.82,89.76
GND on TOP: 104.7,9.09 105.46,9.09 105.82,8.74 109.8,8.74 110.06,8.99 112.55,8.99 112.73,8.81 112.73,8.05 112.32,7.65 111.25,7.65 111.02,7.87 104.7,7.87 104.57,8 104.57,8.97
GND on TOP: 86.18,24.08 88.47,24.08 88.72,23.83 88.72,23.44 88.6,23.32 85.67,23.32 85.55,23.44 85.55,23.65 84.91,24.28 84.91,25.6 85.09,25.78 87.4,25.78 87.5,25.68 87.5,25.27 87.38,25.15 86.13,25.15 86,25.02 86,24.26
GND on TOP: 27.25,13.54 28.02,13.54 28.14,13.41 29.41,13.41 30.43,12.4 30.43,11.89 30.3,11.76 29.16,11.76 28.91,12.01 27.76,12.01 27.25,11.51 26.37,11.51 26.24,11.63 26.24,13.16 26.37,13.28 27,13.28
GND on TOP: 41.99,29.79 46.05,29.79 46.18,29.67 46.18,28.78 46.05,28.65 41.99,28.65 41.86,28.78 41.86,29.67
GND on BOTTOM: 121.36,56.85 122.25,56.85 122.5,56.59 122.5,54.43 122.38,54.31 121.49,54.31 121.36,54.18 121.36,53.04 121.23,52.91 120.73,52.91 120.6,53.04 120.6,56.08
GND on L2-GND: 0.38,89 0.57,89.45 1.02,89.64 134.06,89.64 134.51,89.45 134.7,89 134.7,1.02 134.51,0.57 134.06,0.38 1.02,0.38 0.57,0.57 0.38,1.02 ; 2 cut-outs
GND on L3-POW: 134.06,89.64 134.51,89.45 134.7,89 134.7,1.02 134.51,0.57 134.06,0.38 1.02,0.38 0.57,0.57 0.38,1.02 0.38,89 0.57,89.45 1.02,89.64 ; 5 cut-outs
GND_EARTH on BOTTOM (solid shape): 17.27,78.74 17.27,77.65 16.1,76.48 16.1,72.29 15.49,71.68 12.37,71.68 11.76,72.29 11.76,74.12 11.38,74.5 9.73,74.5 6.76,71.53 3.51,71.53 1.83,73.2 1.83,75.77 3.81,77.75 12.01,77.75 13.72,79.45 16.56,79.45
GND_EARTH on BOTTOM: 0.25,71.55 0.25,89 0.48,89.54 1.02,89.76 51.33,89.76 51.71,89.38 51.71,77.77 50.98,77.04 49.61,77.04 49.2,77.44 35.79,77.44 35.26,76.91 30.96,76.91 30.48,77.39 16.94,77.39 14.35,74.8 9.55,74.8 6.3,71.55
GND_EARTH on L3-POW: 15.51,76.86 14.43,77.94 14.43,89.41 14.66,89.64 51.41,89.64 51.54,89.64 51.77,89.41 51.77,77.65 50.98,76.86
GND_IN on TOP: 18.08,10.26 18.39,10.26 18.59,10.06 18.59,8.43 18.21,8.05 12.8,8.05 12.8,9.83 13.03,10.06 17.88,10.06
GND_IN on TOP: 11.89,13.54 12.14,13.28 12.14,12.32 10.54,10.72 9.35,10.72 8.99,11.07 8.99,13.34 9.19,13.54
GND_IN on TOP: 10.62,63.32 8.79,63.32 8.56,63.55 8.56,67.34 8.66,67.44 9.94,67.44 9.94,67.42 10.08,67.28 10.08,66.17 10.72,65.53 10.72,63.42
GND_IN on TOP: 14.4,73.69 14.4,72.64 14.35,72.59 9.91,72.59 9.55,72.95 9.55,75.56 10.08,76.1 11.99,76.1
GND_IN on L3-POW: 9.17,2.17 8.14,3.2 8.14,10.95 6.63,12.46 0.71,12.46 0.71,12.47 0.48,12.7 0.48,84.1 0.38,84.2 0.38,89.13 0.86,89.61 13.67,89.61 13.79,89.48 13.79,71.02 11.33,68.55 11.33,68.49 11.3,68.47 11.3,65.07 9.55,63.32 8.33,63.32 7.95,63.7 4.65,63.7 4.14,63.2 4.14,29.27 4.7,28.71 6.47,28.71 6.74,28.45 6.74,19.05 10.03,15.76 12.7,15.76 14.24,14.22 14.24,6.48 14.27,6.45 14.27,5.96 10.49,2.17
VBAT_WL_1T1R on TOP: 111.84,21.79 115.27,21.79 116.28,22.81 117.93,22.81 118.19,22.56 118.19,20.9 117.93,20.65 113.87,20.65 113.49,21.03 111.84,21.03 111.71,21.16 111.71,21.67
VBAT_WL_1T1R on TOP: 122.5,36.91 122.5,35.64 122.25,35.38 122.25,33.35 122.12,33.22 120.6,33.22 120.47,33.35 120.47,35.13 121.36,36.02 121.36,36.91 121.49,37.03 122.38,37.03
VBAT_WL_1T1R on BOTTOM: 122.25,35.51 122.25,33.73 121.11,32.59 120.35,32.59 117.55,29.79 117.55,24.84 118.19,24.21 118.19,21.92 117.81,21.54 116.81,21.54 115.3,23.05 115.3,29.4 121.5,35.6 122.16,35.6
VCC2V8_DVP on TOP: 47.83,11.25 48.72,11.25 48.84,11.13 48.84,9.73 47.19,8.08 46.3,8.08 46.18,8.2 46.18,9.35 46.43,9.6 47.19,9.6 47.7,10.11 47.7,11.13
VCC2V8_DVP on TOP: 67.26,12.14 67.26,11.51 65.35,9.6 65.35,8.2 65.48,8.08 66.12,8.08 66.24,8.2 66.24,9.22 68.53,11.51 68.53,12.14 68.4,12.27 67.39,12.27
VCC3V3_PHY0 on TOP: 29.79,43.76 30.43,43.76 31.45,42.75 32.59,42.75 32.72,42.62 32.72,41.99 32.59,41.86 32.08,41.86 31.95,41.99 29.92,41.99 29.67,42.24 29.67,43.64
VCC3V3_PHY0 on L2-GND: 37.62,34.43 36.08,35.97 36.08,37.37 35.33,38.11 33.43,38.11 32.91,38.64 32.91,40.16 32.79,40.27 32.79,41.38 32.69,41.48 31.98,41.48 31.47,41.99 31.34,41.99 31.24,42.09 30.48,42.09 30.3,42.27 30.3,43.11 30.38,43.19 31.11,43.19 31.46,42.84 31.47,42.85 32.38,42.85 32.69,42.55 32.69,42.25 32.77,42.18 35.94,42.18 36.59,41.53 36.59,39.11 38.73,36.97 43.94,36.97 43.98,36.93 44.12,36.93 44.35,36.7 44.35,34.06 44.2,33.91 41,33.91 40.59,34.32 40.59,34.35 40.51,34.43
VCC5V0_M on TOP: 19.13,64.21 24.33,64.21 24.59,63.96 24.59,63.07 24.21,62.69 21.54,62.69 21.41,62.56 21.41,60.66 21.29,60.53 19.25,60.53 19,60.78 19,64.08
VCC5V0_M on BOTTOM: 22.17,65.61 22.17,64.72 21.41,63.96 21.41,62.94 21.54,62.81 24.46,62.81 24.87,63.22 24.87,65.07 24.21,65.74 22.3,65.74
VCC5V0_USB1 on TOP: 122.43,2.11 121.01,2.11 120.68,2.44 120.68,4.32 121.27,4.91 122.14,4.91 122.56,5.33 122.56,11 123.85,12.29 123.85,13.87 124.49,14.5 124.97,14.5 124.97,11.46 123.83,10.31 123.83,4.85 122.66,3.68 122.66,2.34
VCC5V0_USB1 on TOP: 118.44,20.27 118.44,18.24 118.57,18.11 120.6,18.11 120.73,18.24 120.73,20.27 120.6,20.4 118.57,20.4
VCC5V0_USB1 on BOTTOM: 120.07,18.62 118.69,18.62 118.44,18.87 118.44,19.58 120.27,19.58 125.37,14.48 125.37,13.46 125.17,13.26 124.43,13.26 124.31,13.39 124.31,14.33 123.79,14.85 122.14,14.85 120.88,16.1 120.88,17.75 120.07,18.57
VCC5V0_USB2 on TOP: 111.58,3.89 111.58,2.36 111.46,2.24 108.79,2.24 108.53,2.49 108.53,7.44 108.66,7.57 111.07,7.57 111.2,7.44 112.09,7.44 112.22,7.32 112.22,4.52
VCC5V0_USB3 on TOP: 97.61,14.05 97.49,14.17 96.75,14.17 96.75,14.05 96.22,13.51 96.22,9.8 97.36,8.66 97.36,2.39 97.64,2.11 100.15,2.11 100.53,2.49 100.53,4.01 99.14,5.41 99.14,8.59 97.61,10.11
VCC5V0_USB_HOST1 on TOP: 90.63,74.96 90.98,75.31 90.98,76.07 90.65,76.4 89.84,76.4 89.38,76.86 89.38,77.6 90.09,78.31 91.41,78.31 91.9,77.83 91.9,70.43 92.1,70.23 92.1,68.07 92.66,67.51 92.66,66.88 92.56,66.78 91.47,66.78 90.98,67.26 90.98,70.59 90.63,70.94
VCC5V0_USB_HOST1 on BOTTOM: 89.36,73.86 90.12,73.86 90.63,73.36 91.39,73.36 91.9,73.86 91.9,75.77 91.67,76 91.67,77.98 91.34,78.31 88.47,78.31 88.09,77.93 88.09,75.13
VCC5V0_USB_HOST2 on TOP: 89.61,81.1 95.33,81.1 96.09,80.34 96.09,75.06 97.43,73.71 97.43,71.73 97.61,71.55 97.61,70.64 97.54,70.56 95.38,70.56 95.22,70.71 95.22,73.66 94.69,74.19 94.69,79.45 94.44,79.71 89.61,79.71 89.36,79.96 89.36,80.85
VCC5V0_USB_OTG0 on TOP: 125.3,84.66 125.81,84.66 125.93,84.53 125.93,83.39 125.68,83.13 125.68,82.75 125.55,82.63 124.66,82.63 124.28,82.25 124.28,81.99 124.16,81.86 123.65,81.86 123.52,81.99 123.52,83.01 123.77,83.26 125.04,83.26 125.17,83.39 125.17,84.53
VCC5V0_USB_OTG0 on TOP: 130.12,84.66 130.63,84.66 130.76,84.53 130.76,83.26 131.01,83.01 131.7,83.01 132.16,82.55 132.16,81.74 132.03,81.61 131.09,81.61 130.91,81.43 130.91,79.86 131.27,79.5 132.21,79.5 133.65,78.05 133.65,71.75 131.88,69.98 124.74,69.98 124.23,70.48 124.23,73.74 125.35,74.85 125.35,76.25 128.55,79.45 128.78,79.45 129.87,80.54 129.87,83.01 130,83.13 130,84.53
VCC5V0_USB_OTG0 on BOTTOM: 123.65,83.26 124.74,83.26 125.81,82.19 129.62,82.19 130.68,83.26 131.93,83.26 132.18,83.01 132.18,81.41 132,81.23 124.49,81.23 123.39,82.32 123.39,83.01
VCC5V0_USB_OTG0 on BOTTOM: 118.82,56.21 118.82,53.16 119.08,52.91 120.22,52.91 120.35,53.04 120.35,55.83 119.84,56.34 118.95,56.34
VCC5V0_USB_OTG0 on L2-GND: 122.79,70.4 123.81,71.42 128.27,71.42 128.63,71.07 128.63,70.28 128.3,69.95 125.55,69.95 124.89,69.29 124.89,68.35 124.52,67.98 124.52,65.2 120.53,61.21 120.52,61.21 120.32,61.01 120.32,55.47 120.29,55.5 118.49,55.5 117.55,56.44 117.55,56.46 117.12,56.9 117.12,59.03 118.21,60.12 118.21,62.66 118.21,62.66 122.79,67.24
VCC5V_SPK on TOP: 107.01,68.4 106.88,68.28 106.88,67.39 107.01,67.26 108.15,67.26 108.41,67.51 108.41,68.28 108.92,68.78 114.12,68.78 114.25,68.66 114.63,68.66 114.76,68.78 114.76,69.42 114.25,69.93 111.46,69.93 111.33,70.05 108.92,70.05 108.79,69.93 108.79,69.42 107.77,68.4
VCC5V_SPK on TOP: 118.06,69.93 117.81,69.67 117.81,68.91 117.93,68.78 120.22,68.78 120.22,68.17 119.91,67.87 119.91,66.85 120.12,66.65 120.6,66.65 121.08,67.13 121.62,67.13 121.87,67.39 121.87,69.8 121.74,69.93
VCC5V_SPK on BOTTOM: 113.23,68.78 113.36,68.66 118.34,68.66 119.28,67.72 119.28,67.03 119.56,66.75 120.57,66.75 120.73,66.9 120.73,68.02 119.46,69.29 119.08,69.29 118.36,70 113.54,70 113.23,69.7
VCC5V_SYS on TOP: 55.85,75.54 54.61,75.54 54.13,76.02 54.13,76.3 53.52,76.91 53.52,78.26 53.21,78.56 53.21,78.82 51.84,80.19 51.84,85.04 49.73,87.15 27.3,87.15 25.15,84.99 23.27,84.99 22.53,85.72 22.53,89.26 22.91,89.64 53.31,89.64 55.11,87.85 55.11,79.49 56.01,78.59 56.01,75.64 55.85,75.49
VCC5V_SYS on TOP: 61.9,69.39 60.78,68.28 59.64,68.28 57.73,66.37 57.73,65.18 57.84,65.07 62.76,65.07 63.5,65.81 63.5,69.77 63.45,69.82 61.98,69.82 61.9,69.75
VCC5V_SYS on BOTTOM: 21.26,64.21 19.76,64.21 18.9,65.07 18.9,65.79 19.13,66.01 20.98,66.01 21.44,65.56 21.44,64.39
VCC5V_SYS on L2-GND: 25.02,79.88 22.28,77.14 18.49,77.14 17.02,75.67 17.02,66.42 17.5,65.94 20.75,65.94 21.13,65.56 21.13,64.14 21.21,64.06 21.21,60.55 20.93,60.27 15.95,60.27 15.16,61.06 11.94,61.06 10.72,62.28 10.72,81.48 12.95,83.72 13.69,83.72 16.92,86.94 24.46,86.94 25.02,86.39
VCC5V_SYS on L2-GND: 58.29,65.68 60.35,65.68 61.42,66.75 61.42,71.55 60.2,72.77 57.94,72.77 57.3,73.41 57.3,73.89 56.57,74.63 56.57,75.03 56.35,75.25 55.94,75.25 55.75,75.44 55.75,77.22 55.12,77.85 53.14,77.85 51.38,76.1 51.38,71.98 52.5,70.87 57.96,70.87 58.47,70.36 58.47,67.44 58.01,66.98 58.01,65.96
VCC12V_DCIN on TOP: 14.17,82.63 14.17,77.44 17.27,74.35 17.27,66.5 17.25,66.47 15.21,66.47 15.19,66.5 15.19,73.25 12.12,76.33 10.03,76.33 9.35,75.64 9.35,72.77 9.64,72.48 9.64,72 7.67,70.03 4.04,70.03 3.43,69.42 3.43,18.69 6.3,15.82 8.97,15.82 9.6,15.19 12.01,15.19 12.14,15.06 12.14,14.05 12.01,13.92 9.25,13.92 8.79,13.46 8.79,10.92 10.69,9.02 10.69,6.15 11.15,5.69 18.77,5.69 18.87,5.79 18.87,10.24 19,10.36 20.4,10.36 20.65,10.11 20.65,9.22 21.41,8.46 21.41,1.73 21.03,1.35 0.58,1.35 0.38,1.55 0.38,85.57 0.48,85.67 11.13,85.67
VCC12V_DCIN on L2-GND: 0.76,17.75 0.38,17.37 0.38,1.65 0.86,1.17 19.53,1.17 20.14,1.78 20.14,7.21 19.96,7.39 18.75,7.39 18.47,7.11 18.47,5.87 9.3,5.87 8.61,6.55 8.61,13.41 8.64,13.41 8.66,13.44 8.66,17.35 8.25,17.75
VCC_3V3_HUB on TOP: 101.93,40.72 103.45,40.72 103.58,40.59 103.58,40.34 103.45,40.21 101.93,40.21 101.68,39.95 101.68,38.56 101.17,38.05 101.17,36.8 100.69,36.8 100,36.12 100,35.41 100.33,35.08 101.02,35.08 101.17,34.92 101.17,33.5 101.45,33.22 102.18,33.22 102.95,32.46 103.58,32.46 103.71,32.33 103.71,31.95 103.58,31.83 100.46,31.83 100.2,32.08 100.2,34.24 100.15,34.29 98.88,34.29 98.88,36.42 99.49,37.03 99.77,37.03 99.77,40.08 100.15,40.46 100.41,40.46 100.53,40.59 100.53,40.97 100.66,41.1 101.55,41.1
VCC_3V3_HUB on BOTTOM: 105.5,46.29 105.61,46.18 105.61,41.61 105.36,41.35 104.6,41.35 103.71,40.46 100.66,40.46 100.41,40.72 100.41,41.48 100.66,41.73 102.57,41.73 103.07,42.24 103.1,42.24 103.1,42.57 102.92,42.75 100.53,42.75 99.9,43.38 99.9,43.89 99.01,44.78 99.01,45.06 99.16,45.21 100.74,45.21 101.68,44.27 102.18,44.27 102.57,44.65 102.57,45.67 103.19,46.29
VCC_3V3_HUB on BOTTOM: 103.45,32.84 103.84,32.46 111.71,32.46 115.9,36.65 116.66,36.65 116.79,36.53 116.79,35.2 112.65,31.06 101.3,31.06 101.17,31.19 101.17,32.08 101.93,32.84
VCC_3V8 on TOP: 101.55,60.4 101.42,60.27 100.41,60.27 100.28,60.4 100.28,62.56 99.9,62.94 98.4,62.94 98.02,63.32 98.02,64.34 98.15,64.47 98.88,64.47 99.26,64.85 101.3,64.85 101.55,64.59
VCC_3V8 on TOP: 118.95,54.31 118.95,51.89 118.82,51.77 117.42,51.77 117.3,51.64 117.3,50.5 117.42,50.37 121.23,50.37 121.36,50.5 121.36,54.31 121.23,54.43 119.08,54.43
VCC_3V8 on TOP: 107.01,54.31 107.01,52.15 106.88,52.02 104.85,52.02 104.72,51.89 104.72,51 105.36,50.37 108.92,50.37 109.04,50.5 109.04,51.13 108.92,51.26 108.53,51.26 107.65,52.15 107.65,54.31 107.52,54.43 107.14,54.43
VCC_3V8 on TOP: 96.67,51.69 96.9,51.69 97.1,51.49 97.1,48.69 96.89,48.48 95.19,48.48 94.82,48.84 94.82,50.11 95.2,50.5 95.2,54.31 95.33,54.43 96.24,54.43 96.39,54.28 96.39,51.97
VCC_3V8 on BOTTOM: 102.44,54.94 105.71,54.94 106.02,54.64 106.98,54.64 107.14,54.48 107.14,52.17 107.29,52.02 107.29,51.03 107.04,50.77 106.5,50.77 106.27,51 104.6,51 104.52,51.08 104.53,51.09 104.53,52.97 104.14,53.37 102.36,53.37 102.31,53.42 102.31,54.81
VCC_3V8 on L3-POW: 93.24,59.92 95.64,59.92 97.92,62.2 97.92,62.36 97.94,62.38 97.94,63.64 111.38,63.64 113.47,65.74 114.63,65.74 114.83,65.53 114.83,63.63 116.64,61.82 116.64,59.64 116.59,59.59 116.59,58.42 121.42,53.59 121.42,51.59 121.16,51.32 118.9,51.32 116.33,53.89 111.16,53.89 110.67,54.38 110.67,56.41 110.69,56.44 109.66,57.48 104.27,57.48 103.9,57.85 103.84,57.78 96.01,57.78 93.03,54.8 93.03,52.95 94.13,51.84 97.43,51.84 98.45,52.86 100.13,52.86 100.13,55.19 100.43,55.5 101.12,55.5 101.55,55.07 101.55,52.86 106.95,52.86 107.2,52.6 107.2,50.57 107.04,50.41 101.83,50.41 100.17,48.76 92.34,48.76 90.14,50.95 90.14,55.91 92.91,58.67 92.91,59.59
VCC_5V on TOP: 129.62,15.7 130.12,15.19 134.06,15.19 134.32,14.94 134.32,13.03 134.06,12.78 126.95,12.78 126.7,13.03 126.7,15.44 126.95,15.7
VCC_5V on TOP: 25.22,22.56 28.78,22.56 28.91,22.43 28.91,20.4 27.33,20.4 27.15,20.57 24.97,20.57 24.84,20.7 24.84,22.17
VCC_5V on TOP: 82.5,22.94 82.5,20.9 83.41,19.99 83.41,19.71 83.58,19.55 85.08,19.55 85.17,19.63 85.17,22.05 84.66,22.56 84.66,23.06 84.53,23.19 82.75,23.19
VCC_5V on TOP: 32.82,3.51 32.82,2.01 33.1,1.73 92.91,1.73 93.9,2.72 95.38,2.72 95.66,3 95.66,4.19 95.48,4.37 94.39,4.37 93.7,5.05 93.7,7.7 93.57,7.82 90.83,7.82 90.78,7.77 90.78,6.32 90.42,5.97 90.42,5.61 89.59,4.78 35.89,4.78 34.87,3.76 33.07,3.76
VCC_5V on TOP: 120.09,21.92 120.75,21.92 120.9,22.07 120.9,24 120.32,24.59 118.69,24.59 118.57,24.46 118.57,23.57 118.82,23.32 119.58,23.32 119.96,22.94 119.96,22.05
VCC_5V on TOP: 97.26,65.71 97.26,68.35 96.8,68.81 96.49,68.81 95.99,69.32 95.33,69.32 95.15,69.14 95.15,68.2 94.64,67.69 94.36,67.69 94.18,67.51 94.18,66.67 94.44,66.42 94.97,66.42 95.55,65.84 95.55,64.39 96.29,63.65 96.29,62.84 96.52,62.61 97.69,62.61 97.87,62.79 97.87,63.14 97.66,63.35 97.66,65.3
VCC_5V on TOP: 107.01,7.44 107.01,6.81 106.76,6.55 106.76,5.66 106.5,5.41 104.72,5.41 104.47,5.66 104.47,7.44 104.6,7.57 106.88,7.57
VCC_5V on TOP: 105.61,66.5 108.15,66.5 108.53,66.12 108.53,64.34 108.15,63.96 105.49,63.96 105.36,64.08 105.36,66.24
VCC_5V on TOP: 25.1,27.64 25.1,25.98 25.35,25.73 27.25,25.73 27.38,25.86 27.38,27.13 24.84,29.67 24.33,29.67 24.21,29.54 24.21,28.52
VCC_5V on TOP: 13.28,28.65 13.28,20.65 13.92,20.02 15.06,20.02 15.82,19.25 15.82,18.24 15.7,18.11 13.16,18.11 12.14,19.13 10.87,19.13 10.62,18.87 10.62,17.22 11,16.84 12.52,16.84 13.03,16.33 14.43,16.33 14.55,16.21 14.55,15.95 14.3,15.7 13.67,15.7 13.41,15.44 10.11,15.44 8.97,16.59 8.97,17.86 8.46,18.36 7.7,18.36 7.44,18.62 7.44,19.63 7.7,19.89 8.46,19.89 11.05,22.48 11.05,28.6 11.35,28.91 13.03,28.91
VCC_5V on TOP: 95.45,17.42 95.45,15.82 95.58,15.7 96.6,15.7 96.85,15.44 97.61,15.44 97.74,15.57 97.74,16.71 97.1,17.35 97.1,17.65 95.68,17.65
VCC_5V on BOTTOM: 119.08,49.99 118.57,49.48 118.57,48.51 118.92,48.16 120.29,48.16 120.35,48.21 121.11,48.21 121.23,48.34 121.23,49.61 120.6,50.24 120.6,51.38 120.47,51.51 119.2,51.51 119.08,51.38
VCC_5V on BOTTOM: 94.31,1.63 93.14,2.79 93.14,3.76 93.83,4.45 97.66,4.45 99.24,6.02 101.35,6.02 102.46,7.14 115.6,7.14 115.9,6.83 121.39,6.83 122.68,8.13 122.68,10.41 125.58,13.31 125.58,14.61 120.32,19.86 120.32,21.87 119.33,22.86 119.33,24.21 119.63,24.51 120.5,24.51 121.42,23.58 121.42,23.38 121.44,23.37 121.44,22.53 128.68,15.29 128.68,12.67 128.55,12.55 127.56,12.55 125.98,10.97 125.98,2.16 125.45,1.63
VCC_5V on BOTTOM: 91.91,21.15 92.28,20.78 94.41,20.78 97.26,17.93 97.26,10.13 93.55,6.43 90.88,6.43 90.63,6.68 90.63,8.05 91.34,8.76 92.33,8.76 95,11.43 95,12.4 94.64,12.75 94.64,16.66 93.19,18.11 92.33,18.11 91.24,19.2 83.31,19.2 83.13,19.38 83.13,20.9 83.4,21.17 83.43,21.15
VCC_5V on BOTTOM: 98.04,63.07 101.8,63.07 103.33,64.59 108.15,64.59 108.28,64.47 108.28,64.08 108.15,63.96 107.01,63.96 103.71,60.66 98.5,60.66 96.34,58.5 94.95,58.5 94.56,58.12 94.56,54.94 97.74,51.77 99.14,51.77 99.39,51.51 99.39,50.62 99.26,50.5 92.02,50.5 91.64,50.88 91.64,57.61 92.91,58.88 92.91,61.67 93.17,61.93 95.33,61.93 96.09,62.69 96.09,63.45 96.42,63.78 97.49,63.78 97.74,63.53 97.74,63.37
VCC_5V on BOTTOM: 11.89,24.21 12.78,24.21 14.43,22.56 14.43,20.02 16.81,17.63 16.81,13.06 18.29,11.58 18.29,9.14 16.33,7.19 16.33,6.43 15.82,5.92 14.94,5.92 14.3,6.55 14.3,9.35 14.81,9.86 14.81,11.2 14.45,11.56 14.45,16.51 14.81,16.87 14.81,17.48 13.03,19.25 12.14,19.25 11.63,19.76 11.63,23.95
VCC_5V on L2-GND: 119.92,23 119.61,23.31 119.61,24.49 119.81,24.69 119.81,30.68 118.39,32.11 118.39,36.32 119.18,37.11 119.18,40.21 114.95,44.44 114.95,48.89 115.6,49.54 119.89,49.54 120.28,49.15 120.28,47.65 119.52,46.89 119.52,46.1 120.69,44.93 121.59,44.93 122.76,46.1 124.54,46.1 126.85,43.79 126.85,30.37 127.39,29.82 127.39,23.78 126.62,23
VCC_5V on L2-GND: 11,24.36 11,20.04 11.05,19.99 13.59,19.99 14.83,21.23 27.05,21.23 27.15,21.34 27.15,21.84 26.97,22.02 26.06,22.02 25.63,22.45 25.63,25.48 27.03,26.87 27.03,27.41 25.32,29.11 23.14,29.11 19.81,25.78 12.42,25.78
VCC_5V on L3-POW: 116.61,47.51 114.45,49.68 114.45,50.2 114.17,50.47 107.69,50.47 107.58,50.57 107.58,53.54 101.78,53.54 101.38,53.94 98.77,53.94 96.93,52.1 94.08,52.1 93.12,53.06 93.12,54.31 96.19,57.38 96.19,57.56 103.96,57.56 104.09,57.43 107.04,57.43 107.62,56.85 108.56,56.85 108.57,56.86 109.36,56.86 109.37,56.87 110.52,55.73 110.52,54.2 110.99,53.73 115.96,53.73 118.74,50.94 121.16,50.94 121.42,50.67 121.42,48.92 120.01,47.51
VCC_5V on L3-POW: 24.66,10.77 26.52,8.92 26.52,6.48 27.69,5.31 34.26,5.31 35.66,3.91 35.66,2.45 34.84,1.63 16.28,1.63 14.78,3.12 14.78,9.12 16.43,10.77
VCC_12V on TOP: 15.32,62.05 15.32,57.86 14.3,56.85 11.51,56.85 11.25,57.1 11.25,62.18 11.38,62.31 15.06,62.31
VCC_12V on TOP: 67.87,68.73 67.87,68.33 67.77,68.22 67.21,68.22 66.98,68.45 66.98,69.47 66.79,69.66 66.79,69.84 66.78,69.85 66.78,69.88 66.62,70.03 63.14,70.03 62.92,70.26 62.92,71.78 63.02,71.88 65.07,71.88 65.79,72.59 65.79,73.1 65.53,73.36 65.53,74.6 65.07,75.06 65.07,76.02 65.1,76.05 65.74,76.05 66.95,74.83 66.95,71.83 67.84,70.94 67.84,69.72 67.88,69.68 67.88,68.75
VCC_12V on TOP: 18.55,30.37 18.55,28.46 18.47,28.37 17.93,28.37 17.7,28.6 17.7,28.68 17.09,29.29 12.4,29.29 12.27,29.41 12.27,30.94 12.4,31.06 17.86,31.06
VCC_12V on BOTTOM: 59.77,75.06 64.9,75.06 65.25,74.7 65.58,74.7 66.14,75.26 66.14,77.27 65.53,77.88 56.36,77.88 56.16,77.67 56.16,75.69 56.46,75.39 59.44,75.39
VCC_12V on L2-GND: 0.97,89.36 54.08,89.36 55.09,88.34 55.09,85.24 54.84,84.99 54.84,84.2 56.01,84.2 57.12,83.08 57.12,79.68 57.26,79.54 57.26,79.34 57.66,78.94 57.66,75.64 57.38,75.36 56.29,75.36 55.87,75.78 55.87,77.62 55.45,78.04 53.89,78.04 52.27,79.66 52.27,81.22 51.54,81.95 51.54,85.85 51.51,85.88 51.51,85.93 50.29,87.15 16.81,87.15 13.63,83.96 11.14,83.96 10.34,83.16 10.34,61.85 11.34,60.85 14.98,60.85 15.25,60.58 15.25,57.69 13.71,56.15 4.82,56.15 4.76,56.08 4.62,56.08 3.56,55.02 3.56,33.15 4.01,32.69 9.25,32.69 10.08,31.85 13.69,31.85 14.76,30.78 14.76,29.59 14.6,29.44 11,29.44 8.84,27.28 0.74,27.28 0.38,27.64 0.38,88.77
VCC_EDP_OUT on TOP: 6.43,16.21 8.46,16.21 8.71,16.46 8.71,17.6 8.33,17.98 7.44,17.98 7.06,18.36 7.06,19.89 7.44,20.27 8.2,20.27 8.84,20.9 8.84,21.41 8.33,21.92 7.82,21.92 7.19,22.56 7.19,23.44 7.82,24.08 8.46,24.08 8.84,24.46 8.84,25.73 8.59,25.98 5.79,25.98 5.41,25.6 5.41,17.22
VCC_EDP_OUT on BOTTOM: 21.41,52.7 21.41,51.89 21.16,51.64 19.63,51.64 17.86,49.86 17.86,48.72 17.09,48.72 16.71,48.34 16.71,45.92 13.67,42.88 9.98,42.88 9.6,42.49 9.6,24.71 9.22,24.33 7.57,24.33 7.32,24.59 7.32,28.27 7.7,28.65 7.7,44.02 8.46,44.78 12.9,44.78 15.06,46.94 15.06,49.73 18.24,52.91 21.21,52.91
VCC_EDP_OUT_ on BOTTOM: 16.84,54.05 16.84,52.91 16.59,52.65 13.16,52.65 12.78,52.27 11.13,52.27 8.84,49.99 4.65,49.99 4.27,50.37 4.27,51.64 4.52,51.89 7.57,51.89 9.86,54.18 16.71,54.18
VCC_LEDA_TX0 on TOP: 18.11,21.54 23.06,21.54 23.44,21.92 23.44,24.08 23.32,24.21 18.24,24.21 17.98,23.95 17.98,21.67
VCC_LEDA_TX0 on BOTTOM: 17.98,26.11 17.98,22.05 18.24,21.79 18.49,21.79 18.87,22.17 18.87,24.59 19.38,25.1 19.38,26.11 19.25,26.24 18.11,26.24
VCC_LEDK_TX0 on BOTTOM: 18.11,30.18 20.02,30.18 20.4,29.79 20.4,26.24 20.14,25.98 19.76,25.98 19.51,26.24 19.51,29.16 19.38,29.29 18.11,29.29 17.98,29.41 17.98,30.05
VCC_LVDS_OUT on TOP: 27.64,9.86 27.76,9.98 27.76,10.74 27.38,11.13 26.11,11.13 25.86,11.38 25.86,12.78 25.6,13.03 24.33,13.03 22.17,10.87 22.17,10.49 22.3,10.36 23.32,10.36 23.83,9.86
VCC_LVDS_OUT on BOTTOM: 8.84,4.83 8.84,7.62 8.97,7.75 10.24,7.75 10.36,7.62 10.36,6.35 10.74,5.97 12.4,5.97 12.9,6.48 12.9,7.49 13.16,7.75 14.3,7.75 14.55,7.49 14.55,6.35 14.94,5.97 16.46,5.97 16.84,6.35 16.84,7.19 18.57,8.92 21.74,8.92 22.17,9.35 22.17,10.87 22.81,11.51 22.94,11.51 23.57,10.87 24.08,10.87 24.21,10.74 24.21,5.87 22.78,4.45 9.22,4.45 ; 1 cut-out
VCC_LVDS_OUT_ on TOP: 6.17,32.33 9.73,32.33 9.86,32.46 11.3,32.46 11.89,31.88 11.89,30.96 8.94,28.02 4.52,28.02 4.27,28.27 4.27,30.3 4.39,30.43 5.66,30.43 6.05,30.81 6.05,32.21
VCC_LVDS_OUT_ on TOP: 21.16,9.35 22.94,9.35 23.06,9.47 23.06,9.98 22.94,10.11 22.17,10.11 22.17,10.36 21.79,10.74 20.9,10.74 20.78,10.62 20.78,9.73
VCC_LVDS_OUT_ on BOTTOM: 12.01,27.51 14.43,27.51 14.81,27.13 14.81,24.59 15.7,23.7 15.7,19.51 17.04,18.16 17.04,13.31 18.49,11.86 18.49,9.86 18.87,9.47 21.77,9.47 21.97,9.68 21.97,11.71 21.54,12.14 19.76,12.14 17.98,13.92 17.98,18.62 16.84,19.76 16.84,24.21 15.82,25.22 15.82,27.89 15.13,28.59 12.84,28.59 11.06,30.37 11.06,32.42 11,32.49 10.13,32.49 9.86,32.21 9.86,29.67
VCCIO_PHY1 on TOP: 62.18,33.22 62.31,33.1 62.31,29.44 62.23,29.36 61.7,29.36 61.42,29.64 61.42,32.33 61.29,32.46 60.78,32.46 60.66,32.59 60.66,33.1 60.78,33.22
VDD3V3_PCIE30 on TOP: 41.48,27.33 41.48,29.92 41.73,30.18 46.05,30.18 46.43,30.56 46.43,36.14 46.3,36.27 44.53,36.27 44.4,36.14 44.4,31.83 44.15,31.57 41.35,31.57 40.32,30.54 40.32,29.38 39.75,28.8 39.75,27.15 39.78,27.13 41.27,27.13
VDD3V3_PCIE30 on TOP: 49.1,20.27 50.5,20.27 50.62,20.14 50.62,16.46 50.5,16.33 49.73,16.33 47.83,18.24 47.32,18.24 46.05,19.51 44.27,19.51 43.76,20.02 43.76,20.9 44.02,21.16 46.69,21.16 47.83,20.02 48.84,20.02
VDD3V3_PCIE30 on BOTTOM: 46.94,19.51 50.24,19.51 50.5,19.25 50.5,18.49 50.24,18.24 48.84,18.24 48.59,17.98 46.94,17.98 46.81,18.11 46.81,19.38
VDD3V3_PCIE30 on BOTTOM: 45.42,36.53 48.34,36.53 48.46,36.4 48.46,35.64 48.45,35.62 48.46,35.61 48.46,32.21 48.34,32.08 46.69,32.08 46.56,31.95 46.56,21.67 44.91,20.02 44.4,20.02 43.76,20.65 43.76,21.79 45.03,23.06 45.03,36.14
VDD10_PHY0 on TOP: 40.08,33.73 40.21,33.6 40.21,31.45 40.08,31.32 37.92,31.32 37.67,31.57 37.67,33.48 37.92,33.73
VDD10_PHY0 on L2-GND: 37.24,41.41 36.1,42.56 32.85,42.56 32.82,42.6 32.82,42.72 32.54,43 31.84,43 31.27,43.57 30.38,43.57 30.24,43.72 30.24,44.45 30.51,44.72 38.86,44.72 39.51,44.07 39.51,41.68 39.24,41.41
VDD10_PHY0 on L3-POW: 37.99,32.47 37.99,32.51 40.61,35.14 40.61,35.86 41.94,37.19 43.54,37.19 44.63,38.28 44.63,40.11 43.59,41.15 38.57,41.15 38.49,41.22 38.49,41.91 38.76,42.18 39.75,42.18 39.79,42.14 43.54,42.14 45.34,40.34 45.34,35.13 42.06,31.85 38.07,31.85 37.9,32.03 37.9,32.38
VDD10_PHY1 on TOP: 65.74,34.62 66.5,34.62 66.62,34.49 66.62,31.32 66.5,31.19 64.72,31.19 64.49,31.42 63.45,31.42 63.32,31.55 63.32,32.08 63.45,32.21 64.47,32.21 64.72,32.46 65.48,32.46 65.61,32.59 65.61,34.49
VDD_3V3 on TOP: 57.23,25.68 57.23,24.49 57.35,24.36 58.67,24.36 58.67,27.51 58.57,27.61 57.76,27.61 57.66,27.51 57.66,26.54 57.43,26.31 57.43,25.88
VDD_3V3 on TOP: 73.15,14.81 73.18,14.78 73.18,13.72 74.12,12.78 74.12,12.52 74.75,11.89 74.75,8.08 74.63,7.95 73.99,7.95 73.86,8.08 73.86,9.98 71.7,12.14 71.7,14.68 71.83,14.81
VDD_3V3 on TOP: 99.8,34.11 98.76,34.11 98.5,33.86 98.5,31.62 98.53,31.6 99.54,31.6 100.03,32.08 100.03,33.88
VDD_3V3 on TOP: 33.6,25.6 33.6,23.44 34.32,23.44 34.42,23.34 34.42,23.09 34.59,22.91 35.38,22.91 36.3,23.83 38.53,23.83 38.91,24.21 38.91,27.86 37.97,28.8 37.97,30.78 37.36,31.39 36.07,31.39 35.99,31.32 35.99,30.71 36.04,30.66 36.78,30.66 36.78,30.63 37.16,30.25 37.16,28.52 38.18,27.51 38.18,26.97 37.77,26.57 37.77,25.2 37.67,25.1 35,25.1 33.73,26.37 32.84,26.37 32.72,26.24 32.72,25.98 32.97,25.73 33.48,25.73
VDD_3V3 on TOP: 68.02,24.59 67.89,24.71 67.89,27.66 67.84,27.71 67.84,32.41 68.17,32.74 68.88,32.74 69.04,32.59 69.04,24.71 68.91,24.59
VDD_3V3 on TOP: 63.27,27.64 62.56,27.64 62.33,27.41 62.33,24.74 62.45,24.63 63.06,24.63 63.12,24.69 63.12,25.73 63.2,25.81 63.4,25.81 63.5,25.91 63.5,27.41
VDD_3V3 on TOP: 122.76,34.24 124.66,34.24 124.79,34.37 124.79,35.26 125.3,35.76 125.3,37.67 124.66,38.3 123.27,38.3 123.14,38.18 123.14,36.91 122.89,36.65 122.89,35.51 122.63,35.26 122.63,34.37
VDD_3V3 on TOP: 13.79,13.54 14.3,13.54 14.43,13.41 14.43,11 13.67,10.24 13.03,10.24 12.52,9.73 12.52,6.43 12.27,6.17 11.2,6.17 10.95,6.43 10.95,10.69 12.52,12.27 12.52,13.79 12.65,13.92 13.41,13.92
